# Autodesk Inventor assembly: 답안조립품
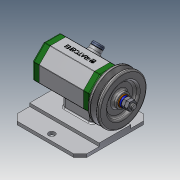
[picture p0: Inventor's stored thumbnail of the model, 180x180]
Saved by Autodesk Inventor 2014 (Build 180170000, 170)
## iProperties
Created: 2018-06
Part Number: 답안조립품
Document SubType Name: Assembly
Designer: NET
Author: NET
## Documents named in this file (16)
- C:\Users\NET\Desktop\480607V1014\답안조립품.iam
- C:\Users\NET\Desktop\480607V1014\본체.ipt
- C:\Users\NET\Desktop\480607V1014\베어링 15x32x9.ipt
- C:\Users\NET\Desktop\480607V1014\축.ipt
- C:\Users\NET\Desktop\480607V1014\뒤커버.ipt
- C:\Users\NET\Desktop\480607V1014\앞커버.ipt
- C:\Users\NET\Desktop\480607V1014\오일 실 15 25 7.ipt
- C:\Users\NET\Desktop\480607V1014\볼트 M4x12.ipt
- C:\Users\NET\Desktop\480607V1014\키 3x3x12.ipt
- 키 3x3x12.ipt
- C:\Users\NET\Desktop\480607V1014\V벨트풀리.ipt
- C:\Users\NET\Desktop\480607V1014\와셔 8x17.ipt
- C:\Users\NET\Desktop\480607V1014\스프링와셔 8.ipt
- C:\Users\NET\Desktop\480607V1014\너트 M8.ipt
- 너트 M8.ipt
- C:\Users\NET\Desktop\480607V1014\고무캡.ipt
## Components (2 placed, 2 different names)
1. V벨트풀리:1
2. 고무캡:1
